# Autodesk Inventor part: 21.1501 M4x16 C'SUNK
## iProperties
Created: 2006-12
Part Number: 21.1501 M4x16 C'SUNK
Material: Steel, Mild
Description: Hexagon socket countersunk head cap screws
Document SubType Name: Modeling
Standard: DIN 7991
Designer: Andy Moles
Standards Organization: DIN
Language: en-US
Size Designation: M4x16
Categories: <MemberInstance Version="R10.0.0"><Categories><Category DisplayName="Fasteners" InternalName="e4da775c-781d-43d5-af7c-5136215cf5a6" Mnemonic="FSTN"><Category Di
Density: 7.86 g/cm^3
Author: Andy Moles
Revision Number: 1
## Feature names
1. Revolution1
2. Extrusion1
3. Fillet1
4. Chamfer1
